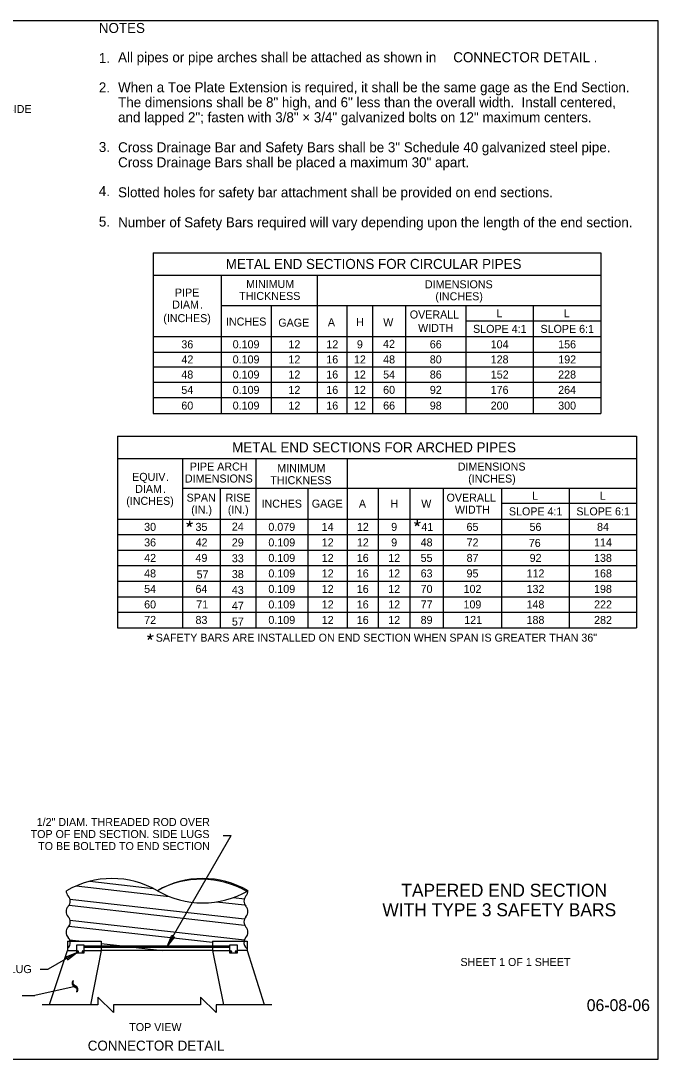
# Model space of a CAD drawing. Extents: x 99862 to 103151, y 100000 to 102076.
# Drawn here: x 101876 to 103151, y 100000 to 102076 of the extents above; entities that cross this region are included whole.
import ezdxf

# ---------------------------------------------------------------- set-up
doc = ezdxf.new("R2010")
doc.units = 0
for name, color, linetype in [('Level 1', 7, 'Continuous'), ('Level 11', 7, 'Continuous'), ('Level 15', 7, 'Continuous'), ('Level 18', 7, 'Continuous'), ('Level 19', 7, 'Continuous'), ('Level 20', 7, 'Continuous'), ('Level 6', 7, 'Continuous'), ('Level 60', 7, 'Continuous'), ('Level 62', 7, 'Continuous')]:
    doc.layers.add(name, color=color, linetype=linetype)

msp = doc.modelspace()

# ---------------------------------------------------------------- linework, layer by layer
at = {"layer": 'Level 1'}
msp.add_lwpolyline([(99862, 99999.5), (103151, 99999.5), (103151, 102075.5), (99862, 102075.5)], close=True, dxfattribs=at)
at = {"layer": 'Level 15'}
for p, q in [((102169.3, 100226.1), (102296.8, 100446.9)), ((102280.8, 100446.9), (102296.8, 100446.9)), ((101987.4, 100212.2), (101931.1, 100179.7)), ((101915.1, 100179.7), (101931.1, 100179.7))]:
    msp.add_line(p, q, dxfattribs=at)
for points in [[(102169.3, 100226.1), (102178.1, 100247.3), (102180.2, 100244.9), (102183.3, 100244.3)], [(101987.4, 100212.2), (101966.2, 100203.3), (101968.6, 100201.3), (101969.2, 100198.2)]]:
    msp.add_lwpolyline(points, close=True, dxfattribs=at)
for points in [[(102148.6, 100108.3), (102061.4, 100108.3), (102061.4, 100092.8), (102030.5, 100123.8), (102030.5, 100108.3), (101918.9, 100108.3)], [(102377.9, 100108.3), (102266.6, 100108.3), (102266.6, 100092.8), (102235.7, 100123.8), (102235.7, 100108.3), (102148.6, 100108.3)]]:
    msp.add_lwpolyline(points, dxfattribs=at)
at = {"layer": 'Level 18'}
for p, q in [((101969.2, 100235.2), (102037.1, 100235.2)), ((101969.2, 100235.2), (101969.2, 100217)), ((102037.1, 100235.2), (102037.1, 100226.1)), ((102259.7, 100235.2), (102328.8, 100235.2)), ((102259.7, 100235.2), (102259.7, 100226.1)), ((102328.8, 100235.2), (102328.8, 100217)), ((101933.6, 100108.7), (101969.2, 100217)), ((102002.9, 100226.1), (102293.7, 100226.1)), ((102002.9, 100223.6), (102293.7, 100223.6)), ((102037.1, 100217), (102015.2, 100108.5)), ((102037.1, 100223.6), (102037.1, 100217)), ((102259.7, 100223.6), (102259.7, 100217)), ((102259.7, 100217), (102281.6, 100108.5)), ((102328.8, 100217), (102363.1, 100109))]:
    msp.add_line(p, q, dxfattribs=at)
for points in [[(102002.9, 100227.7), (101987.4, 100227.7), (101987.4, 100212.2), (102002.9, 100212.2)], [(102309.2, 100227.7), (102293.7, 100227.7), (102293.7, 100212.2), (102309.2, 100212.2)]]:
    msp.add_lwpolyline(points, close=True, dxfattribs=at)
for centre, start, end in [((101990.1, 100214.6), 0, 180), ((101990.1, 100214.6), 180, 0), ((102000.2, 100214.6), 0, 180), ((102000.2, 100214.6), 180, 0), ((102296.4, 100214.6), 0, 180), ((102296.4, 100214.6), 180, 0), ((102306.5, 100214.6), 0, 180), ((102306.5, 100214.6), 180, 0)]:
    msp.add_arc(centre, 1.61, start, end, dxfattribs=at)
at = {"layer": 'Level 19'}
for p, q in [((102141.1, 101611.9), (102141.1, 101290.2)), ((102141.1, 101611.9), (103036.1, 101611.9)), ((103036.1, 101611.9), (103036.1, 101290.2)), ((102141.1, 101566.9), (103036.1, 101566.9)), ((102276.7, 101566.9), (102276.7, 101290.2)), ((102469.1, 101566.9), (102469.1, 101290.2)), ((102276.7, 101506.2), (103036.1, 101506.2)), ((102376.6, 101506.2), (102376.6, 101290.2)), ((102528.3, 101506.2), (102528.3, 101290.2)), ((102579.5, 101506.2), (102579.5, 101290.2)), ((102645.3, 101506.2), (102645.3, 101290.2)), ((102766.1, 101506.2), (102766.1, 101290.2)), ((102901.1, 101506.2), (102901.1, 101290.2)), ((103036.1, 101475.2), (102766.1, 101475.2)), ((102141.1, 101444.2), (103036.1, 101444.2)), ((102141.1, 101413.2), (103036.1, 101413.2)), ((102141.1, 101383.7), (103036.1, 101383.7)), ((102141.1, 101353), (103036.1, 101353)), ((102141.1, 101322.2), (103036.1, 101322.2)), ((102141.1, 101290.2), (103036.1, 101290.2)), ((102069.4, 101245.2), (102069.4, 100862.2)), ((102069.4, 101245.2), (103107.7, 101245.2)), ((103107.7, 101245.2), (103107.7, 100862.2)), ((102069.4, 101200.2), (103107.7, 101200.2)), ((102199.4, 101200.2), (102199.4, 100862.2)), ((102345.9, 101200.2), (102345.9, 100862.2)), ((102528.8, 101200.2), (102528.8, 100862.2)), ((102199.4, 101141.2), (103107.7, 101141.2)), ((102274.9, 101141.2), (102274.9, 100862.2)), ((102450.2, 101141.2), (102450.2, 100862.2)), ((102590.7, 101141.2), (102590.7, 100862.2)), ((102654.2, 101141.2), (102654.2, 100862.2)), ((102720.6, 101141.2), (102720.6, 100862.2)), ((102837.7, 101141.2), (102837.7, 100862.2)), ((102972.7, 101141.2), (102972.7, 100862.2)), ((103107.7, 101110.2), (102837.7, 101110.2)), ((102069.4, 101079.2), (103107.7, 101079.2)), ((102207.5, 101071.3), (102213.5, 101069.4)), ((102209.8, 101064.3), (102213.5, 101069.4)), ((102213.5, 101075.7), (102213.5, 101069.4)), ((102219.5, 101071.3), (102213.5, 101069.4)), ((102217.2, 101064.3), (102213.5, 101069.4)), ((102663, 101072.8), (102669, 101070.8)), ((102665.3, 101065.7), (102669, 101070.8)), ((102669, 101077.1), (102669, 101070.8)), ((102675, 101072.8), (102669, 101070.8)), ((102672.7, 101065.7), (102669, 101070.8)), ((102069.4, 101048.2), (103107.7, 101048.2)), ((102069.4, 101017.2), (103107.7, 101017.2)), ((102069.4, 100986.2), (103107.7, 100986.2)), ((102069.4, 100955.2), (103107.7, 100955.2)), ((102069.4, 100924.2), (103107.7, 100924.2)), ((102069.4, 100893.2), (103107.7, 100893.2)), ((102069.4, 100862.2), (103107.7, 100862.2)), ((102128.7, 100845.9), (102134.7, 100843.9)), ((102131, 100838.8), (102134.7, 100843.9)), ((102134.7, 100850.2), (102134.7, 100843.9)), ((102140.7, 100845.9), (102134.7, 100843.9)), ((102138.4, 100838.8), (102134.7, 100843.9))]:
    msp.add_line(p, q, dxfattribs=at)
at = {"layer": 'Level 20'}
for p, q in [((101979.1, 100153), (101978.8, 100151.2)), ((101978.8, 100151.2), (101979, 100149.5)), ((101979, 100149.5), (101979.6, 100147.9)), ((101979.8, 100154.8), (101979.1, 100153)), ((101979.6, 100147.9), (101981.4, 100145.8)), ((101981.7, 100155.9), (101979.8, 100154.8)), ((101980.7, 100151.9), (101980.9, 100153.6)), ((101980.8, 100150.5), (101980.7, 100151.9)), ((101981.3, 100149.3), (101980.8, 100150.5)), ((101980.9, 100153.6), (101981.7, 100155.9)), ((101982.6, 100147.8), (101981.3, 100149.3)), ((101984.6, 100146.4), (101982.6, 100147.8)), ((101988, 100144.1), (101984.6, 100146.4)), ((101878.8, 100126.6), (101904.3, 100126.6)), ((101984.6, 100145), (101904.3, 100126.6)), ((101981.4, 100145.8), (101985, 100143.3)), ((101985, 100143.3), (101987, 100141.9)), ((101987, 100141.9), (101988, 100140.8)), ((101988.5, 100137.8), (101987.6, 100134.2)), ((101987.6, 100134.2), (101989.4, 100135.3)), ((101989.6, 100142.2), (101988, 100144.1)), ((101988, 100140.8), (101988.4, 100139.4)), ((101988.4, 100139.4), (101988.5, 100137.8)), ((101989.4, 100135.3), (101990.1, 100137.3)), ((101990.2, 100140.6), (101989.6, 100142.2)), ((101990.1, 100137.3), (101990.4, 100139)), ((101990.4, 100139), (101990.2, 100140.6))]:
    msp.add_line(p, q, dxfattribs=at)
at = {"layer": 'Level 6'}
for p, q in [((102014.2, 100355.2), (102140.8, 100340.9)), ((101986.8, 100345.9), (102172.8, 100324.9)), ((101974.4, 100319.6), (102323.7, 100280.1)), ((102267.7, 100314.2), (102323.2, 100308)), ((102301.3, 100322.8), (102323.2, 100320.3)), ((101972.6, 100307.4), (102323.7, 100267.8)), ((101974.4, 100277.8), (102323.6, 100238.4)), ((101972.4, 100265.7), (102259.7, 100233.2)), ((101973.8, 100238), (101998.2, 100235.2)), ((102037.1, 100230.8), (102079.2, 100226.1)), ((101969.2, 100217), (101987.4, 100217)), ((102002.9, 100217), (102037.1, 100217)), ((102259.8, 100217), (102037.1, 100217)), ((102100.7, 100223.6), (102159.1, 100217)), ((102259.7, 100217), (102293.7, 100217)), ((102328.8, 100217), (102309.2, 100217))]:
    msp.add_line(p, q, dxfattribs=at)
for centre, radius, start, end in [((102058.5, 100179.3), 181.4, 60, 120), ((102239.9, 100179.3), 181.4, 60, 120), ((102237.3, 100179), 180.4, 59.8127, 119.2392), ((101981.9, 100336.4), 15.1, 180.0381, 223.1116), ((102239.9, 100493.5), 181.4, 240, 300), ((102315.4, 100336.4), 15.1, 316.8884, 359.9619), ((101959.8, 100315.5), 15.1, 316.8884, 43.1116), ((102337.5, 100315.5), 15.1, 136.8884, 223.1116), ((101981.9, 100294.8), 15.1, 136.8884, 223.1116), ((102315.4, 100294.8), 15.1, 316.8884, 43.1116), ((101959.8, 100273.9), 15.1, 316.8884, 43.1116), ((102337.5, 100273.9), 15.1, 136.8884, 223.1116), ((101981.9, 100253.3), 15.1, 136.8884, 223.1116), ((102315.4, 100253.3), 15.1, 316.8884, 43.1116), ((101959.8, 100232.4), 15.1, 308.3919, 10.768), ((101959.8, 100232.4), 15.1, 10.768, 43.1116), ((102337.5, 100232.6), 15.1, 169.9575, 234.8817), ((102337.5, 100232.6), 15.1, 136.8884, 169.9575)]:
    msp.add_arc(centre, radius, start, end, dxfattribs=at)
at = {"layer": 'Level 60'}
msp.add_line((103151, 102075.5), (103151, 102075.5), dxfattribs=at)

# ---------------------------------------------------------------- texts
at = {"layer": 'Level 11'}
msp.add_text('06-08-06', height=23.62, dxfattribs=at).set_placement((103008, 100095.8))
at = {"layer": 'Level 19'}
for s, height, p in [('METAL END SECTIONS FOR CIRCULAR PIPES', 20, (102286, 101579.4)), ('PIPE', 16, (102184.4, 101524.2)), ('MINIMUM', 16, (102326.7, 101541.4)), ('DIMENSIONS', 16, (102684.4, 101540.7)), ('THICKNESS', 16, (102312.8, 101517.4)), ('(INCHES)', 16, (102705.2, 101516.7)), ('DIAM', 16, (102178.9, 101500.2)), ('.', 16, (102234.5, 101500.2)), ('OVERALL', 16, (102654.1, 101480.3)), ('L', 16, (102827.3, 101482.7)), ('L', 16, (102962.3, 101482.7)), ('(INCHES)', 16, (102161.1, 101473)), ('INCHES', 16, (102286.4, 101466.2)), ('GAGE', 16, (102391.1, 101464)), ('A', 16, (102490.2, 101464.7)), ('H', 16, (102546.7, 101465)), ('W', 16, (102600.9, 101464.9)), ('WIDTH', 16, (102670.7, 101453.5)), ('SLOPE 4:1', 16, (102780.6, 101451.6)), ('SLOPE 6:1', 16, (102915.5, 101451.6)), ('36', 16, (102197.2, 101420.7)), ('0.109', 16, (102299.9, 101420.7)), ('12', 16, (102411.4, 101420.7)), ('12', 16, (102487.2, 101420.7)), ('9', 16, (102548.3, 101420.7)), ('42', 16, (102600.6, 101421.6)), ('66', 16, (102694.1, 101420.7)), ('104', 16, (102815.9, 101420.7)), ('156', 16, (102950.9, 101420.7)), ('42', 16, (102197.4, 101390.5)), ('0.109', 16, (102299.9, 101390.5)), ('12', 16, (102411.4, 101390.5)), ('16', 16, (102487.1, 101390.5)), ('12', 16, (102542.4, 101390.5)), ('48', 16, (102600.8, 101390.5)), ('80', 16, (102694.1, 101390.5)), ('128', 16, (102815.9, 101390.5)), ('192', 16, (102951.1, 101390.5)), ('48', 16, (102197.2, 101360.3)), ('0.109', 16, (102299.9, 101360.3)), ('12', 16, (102411.4, 101360.3)), ('16', 16, (102487.1, 101360.3)), ('12', 16, (102542.4, 101360.3)), ('54', 16, (102600.8, 101360.3)), ('86', 16, (102694.1, 101360.3)), ('152', 16, (102816.1, 101360.3)), ('228', 16, (102950.9, 101360.3)), ('54', 16, (102197.2, 101329.6)), ('0.109', 16, (102299.9, 101329.6)), ('12', 16, (102411.4, 101329.6)), ('16', 16, (102487.1, 101329.6)), ('12', 16, (102542.4, 101329.6)), ('60', 16, (102600.8, 101329.6)), ('92', 16, (102694.2, 101329.6)), ('176', 16, (102815.9, 101329.6)), ('264', 16, (102950.9, 101329.6)), ('60', 16, (102197.2, 101298.2)), ('0.109', 16, (102299.9, 101298.2)), ('12', 16, (102411.4, 101298.2)), ('16', 16, (102487.1, 101298.2)), ('12', 16, (102542.4, 101298.2)), ('66', 16, (102600.8, 101298.2)), ('98', 16, (102694.1, 101298.2)), ('200', 16, (102815.9, 101298.2)), ('300', 16, (102950.9, 101298.2)), ('METAL END SECTIONS FOR ARCHED PIPES', 20, (102298.8, 101212.7)), ('PIPE ARCH', 16, (102214.2, 101176.4)), ('MINIMUM', 16, (102389.1, 101173.1)), ('DIMENSIONS', 16, (102750, 101176.3)), ('EQUIV', 16, (102098.8, 101155.7)), ('DIMENSIONS', 16, (102204.4, 101152.4)), ('THICKNESS', 16, (102375.2, 101149.1)), ('(INCHES)', 16, (102770.9, 101152.3)), ('DIAM', 16, (102104.8, 101131.7)), ('.', 16, (102166.4, 101155.7)), ('(INCHES)', 16, (102087, 101107.7)), ('.', 16, (102160.4, 101131.7)), ('SPAN', 16, (102207.7, 101114.1)), ('RISE', 16, (102285.7, 101114.1)), ('OVERALL', 16, (102727.6, 101114.2)), ('L', 16, (102898.9, 101117.8)), ('L', 16, (103033.9, 101117.8)), ('(IN.)', 16, (102216.9, 101090.1)), ('(IN.)', 16, (102290.2, 101090.1)), ('INCHES', 16, (102357.6, 101102.2)), ('GAGE', 16, (102458.1, 101102.2)), ('A', 16, (102552.3, 101102.2)), ('H', 16, (102615.3, 101102.2)), ('W', 16, (102677, 101102.2)), ('WIDTH', 16, (102744.3, 101090.2)), ('SLOPE 4:1', 16, (102852.3, 101086.7)), ('SLOPE 6:1', 16, (102987.2, 101086.7)), ('30', 16, (102122.8, 101055.7)), ('35', 16, (102225.5, 101055.7)), ('24', 16, (102298.2, 101056.3)), ('0.079', 16, (102371.3, 101055.7)), ('14', 16, (102477.8, 101055.7)), ('12', 16, (102548.3, 101055.7)), ('9', 16, (102616.9, 101055.7)), ('41', 16, (102677.3, 101055.7)), ('65', 16, (102767.6, 101055.7)), ('56', 16, (102893.6, 101055.7)), ('84', 16, (103028.6, 101055.7)), ('36', 16, (102122.8, 101024.7)), ('42', 16, (102225.7, 101024.7)), ('29', 16, (102298.2, 101024.7)), ('0.109', 16, (102371.3, 101024.7)), ('12', 16, (102478, 101024.7)), ('12', 16, (102548.3, 101024.7)), ('9', 16, (102616.9, 101024.7)), ('48', 16, (102675.8, 101024.7)), ('72', 16, (102767.7, 101024.7)), ('76', 16, (102892.1, 101023.6)), ('114', 16, (103022.6, 101024.7)), ('42', 16, (102122.9, 100993.7)), ('49', 16, (102225.5, 100993.7)), ('33', 16, (102298.2, 100993)), ('0.109', 16, (102371.3, 100993.7)), ('12', 16, (102478, 100993.7)), ('16', 16, (102548.1, 100993.7)), ('12', 16, (102611, 100993.7)), ('55', 16, (102675.8, 100993.7)), ('87', 16, (102767.7, 100993.7)), ('92', 16, (102893.8, 100993.7)), ('138', 16, (103022.6, 100993.7)), ('48', 16, (102122.8, 100962.7)), ('57', 16, (102227.7, 100960.7)), ('38', 16, (102298.2, 100961.4)), ('0.109', 16, (102371.3, 100962.7)), ('12', 16, (102478, 100962.7)), ('16', 16, (102548.1, 100962.7)), ('12', 16, (102611, 100962.7)), ('63', 16, (102675.8, 100962.7)), ('95', 16, (102767.6, 100962.7)), ('112', 16, (102887.7, 100962.7)), ('168', 16, (103022.6, 100962.7)), ('54', 16, (102122.8, 100931.7)), ('64', 16, (102225.5, 100931.7)), ('43', 16, (102298.2, 100929.7)), ('0.109', 16, (102371.3, 100931.7)), ('12', 16, (102478, 100931.7)), ('16', 16, (102548.1, 100931.7)), ('12', 16, (102611, 100931.7)), ('70', 16, (102675.8, 100931.7)), ('102', 16, (102761.7, 100931.7)), ('132', 16, (102887.7, 100931.7)), ('198', 16, (103022.6, 100931.7)), ('60', 16, (102122.8, 100900.7)), ('71', 16, (102227, 100900.7)), ('0.109', 16, (102371.3, 100900.7)), ('12', 16, (102478, 100900.7)), ('16', 16, (102548.1, 100900.7)), ('12', 16, (102611, 100900.7)), ('77', 16, (102675.9, 100900.7)), ('109', 16, (102761.5, 100900.7)), ('148', 16, (102887.6, 100900.7)), ('222', 16, (103022.7, 100900.7)), ('47', 16, (102298.3, 100898.1)), ('72', 16, (102122.9, 100869.7)), ('83', 16, (102225.5, 100869.7)), ('57', 16, (102298.3, 100866.4)), ('0.109', 16, (102371.3, 100869.7)), ('12', 16, (102478, 100869.7)), ('16', 16, (102548.1, 100869.7)), ('12', 16, (102611, 100869.7)), ('89', 16, (102675.8, 100869.7)), ('121', 16, (102763, 100869.7)), ('188', 16, (102887.6, 100869.7)), ('282', 16, (103022.7, 100869.7)), ('SAFETY BARS ARE INSTALLED ON END SECTION WHEN SPAN IS GREATER THAN 36"', 16, (102146, 100834.3))]:
    msp.add_text(s, height=height, dxfattribs=at).set_placement(p)
at = {"layer": 'Level 20'}
for s, height, p in [('NOTES', 20, (102032.2, 102051.1)), ('1.', 20, (102032.2, 101991.1)), ('All pipes or pipe arches shall be attached as shown in ', 20, (102070.7, 101992.6)), ('CONNECTOR DETAIL', 20, (102741.1, 101992.6)), ('.', 20, (103021.8, 101992.6)), ('2.', 20, (102032.2, 101932.2)), ('When a Toe Plate Extension is required, it shall be the same gage as the End Section.', 20, (102070.7, 101932.6)), ('The dimensions shall be 8" high, and 6" less than the overall width.  Install centered,', 20, (102070.7, 101902.6)), ('FLATTEN END, THEN BEND OUTSIDE', 16, (101514.8, 101891.1)), ('and lapped 2"; fasten with 3/8" × 3/4" galvanized bolts on 12" maximum centers.', 20, (102070.7, 101872.6)), ('3.', 20, (102032.2, 101813.1)), ('Cross Drainage Bar and Safety Bars shall be 3" Schedule 40 galvanized steel pipe.', 20, (102070.7, 101812.6)), ('Cross Drainage Bars shall be placed a maximum 30" apart.', 20, (102070.7, 101782.6)), ('4.', 20, (102032.2, 101725)), ('Slotted holes for safety bar attachment shall be provided on end sections.', 20, (102070.7, 101722.6)), ('5.', 20, (102032.2, 101664.1)), ('Number of Safety Bars required will vary depending upon the length of the end section. ', 20, (102070.7, 101662.6)), ('1/2" DIAM. THREADED ROD OVER', 16, (101907.9, 100465.7)), ('TOP OF END SECTION. SIDE LUGS', 16, (101895.7, 100441.7)), ('TO BE BOLTED TO END SECTION', 16, (101910.8, 100417.7)), ('SIDE LUG', 16, (101798, 100171.7)), ('TOP VIEW', 16, (102093, 100055.8)), ('CONNECTOR DETAIL', 20, (102010, 100016.7))]:
    msp.add_text(s, height=height, dxfattribs=at).set_placement(p)
at = {"layer": 'Level 62'}
for s, height, p in [('TAPERED END SECTION', 26, (102637.1, 100324.3)), ('WITH TYPE 3 SAFETY BARS', 26, (102599.3, 100285.3)), ('SHEET 1 OF 1 SHEET', 16, (102755.4, 100185.9))]:
    msp.add_text(s, height=height, dxfattribs=at).set_placement(p)

doc.saveas('drawing.dxf')
